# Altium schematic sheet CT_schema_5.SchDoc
size 385 x 355 mm
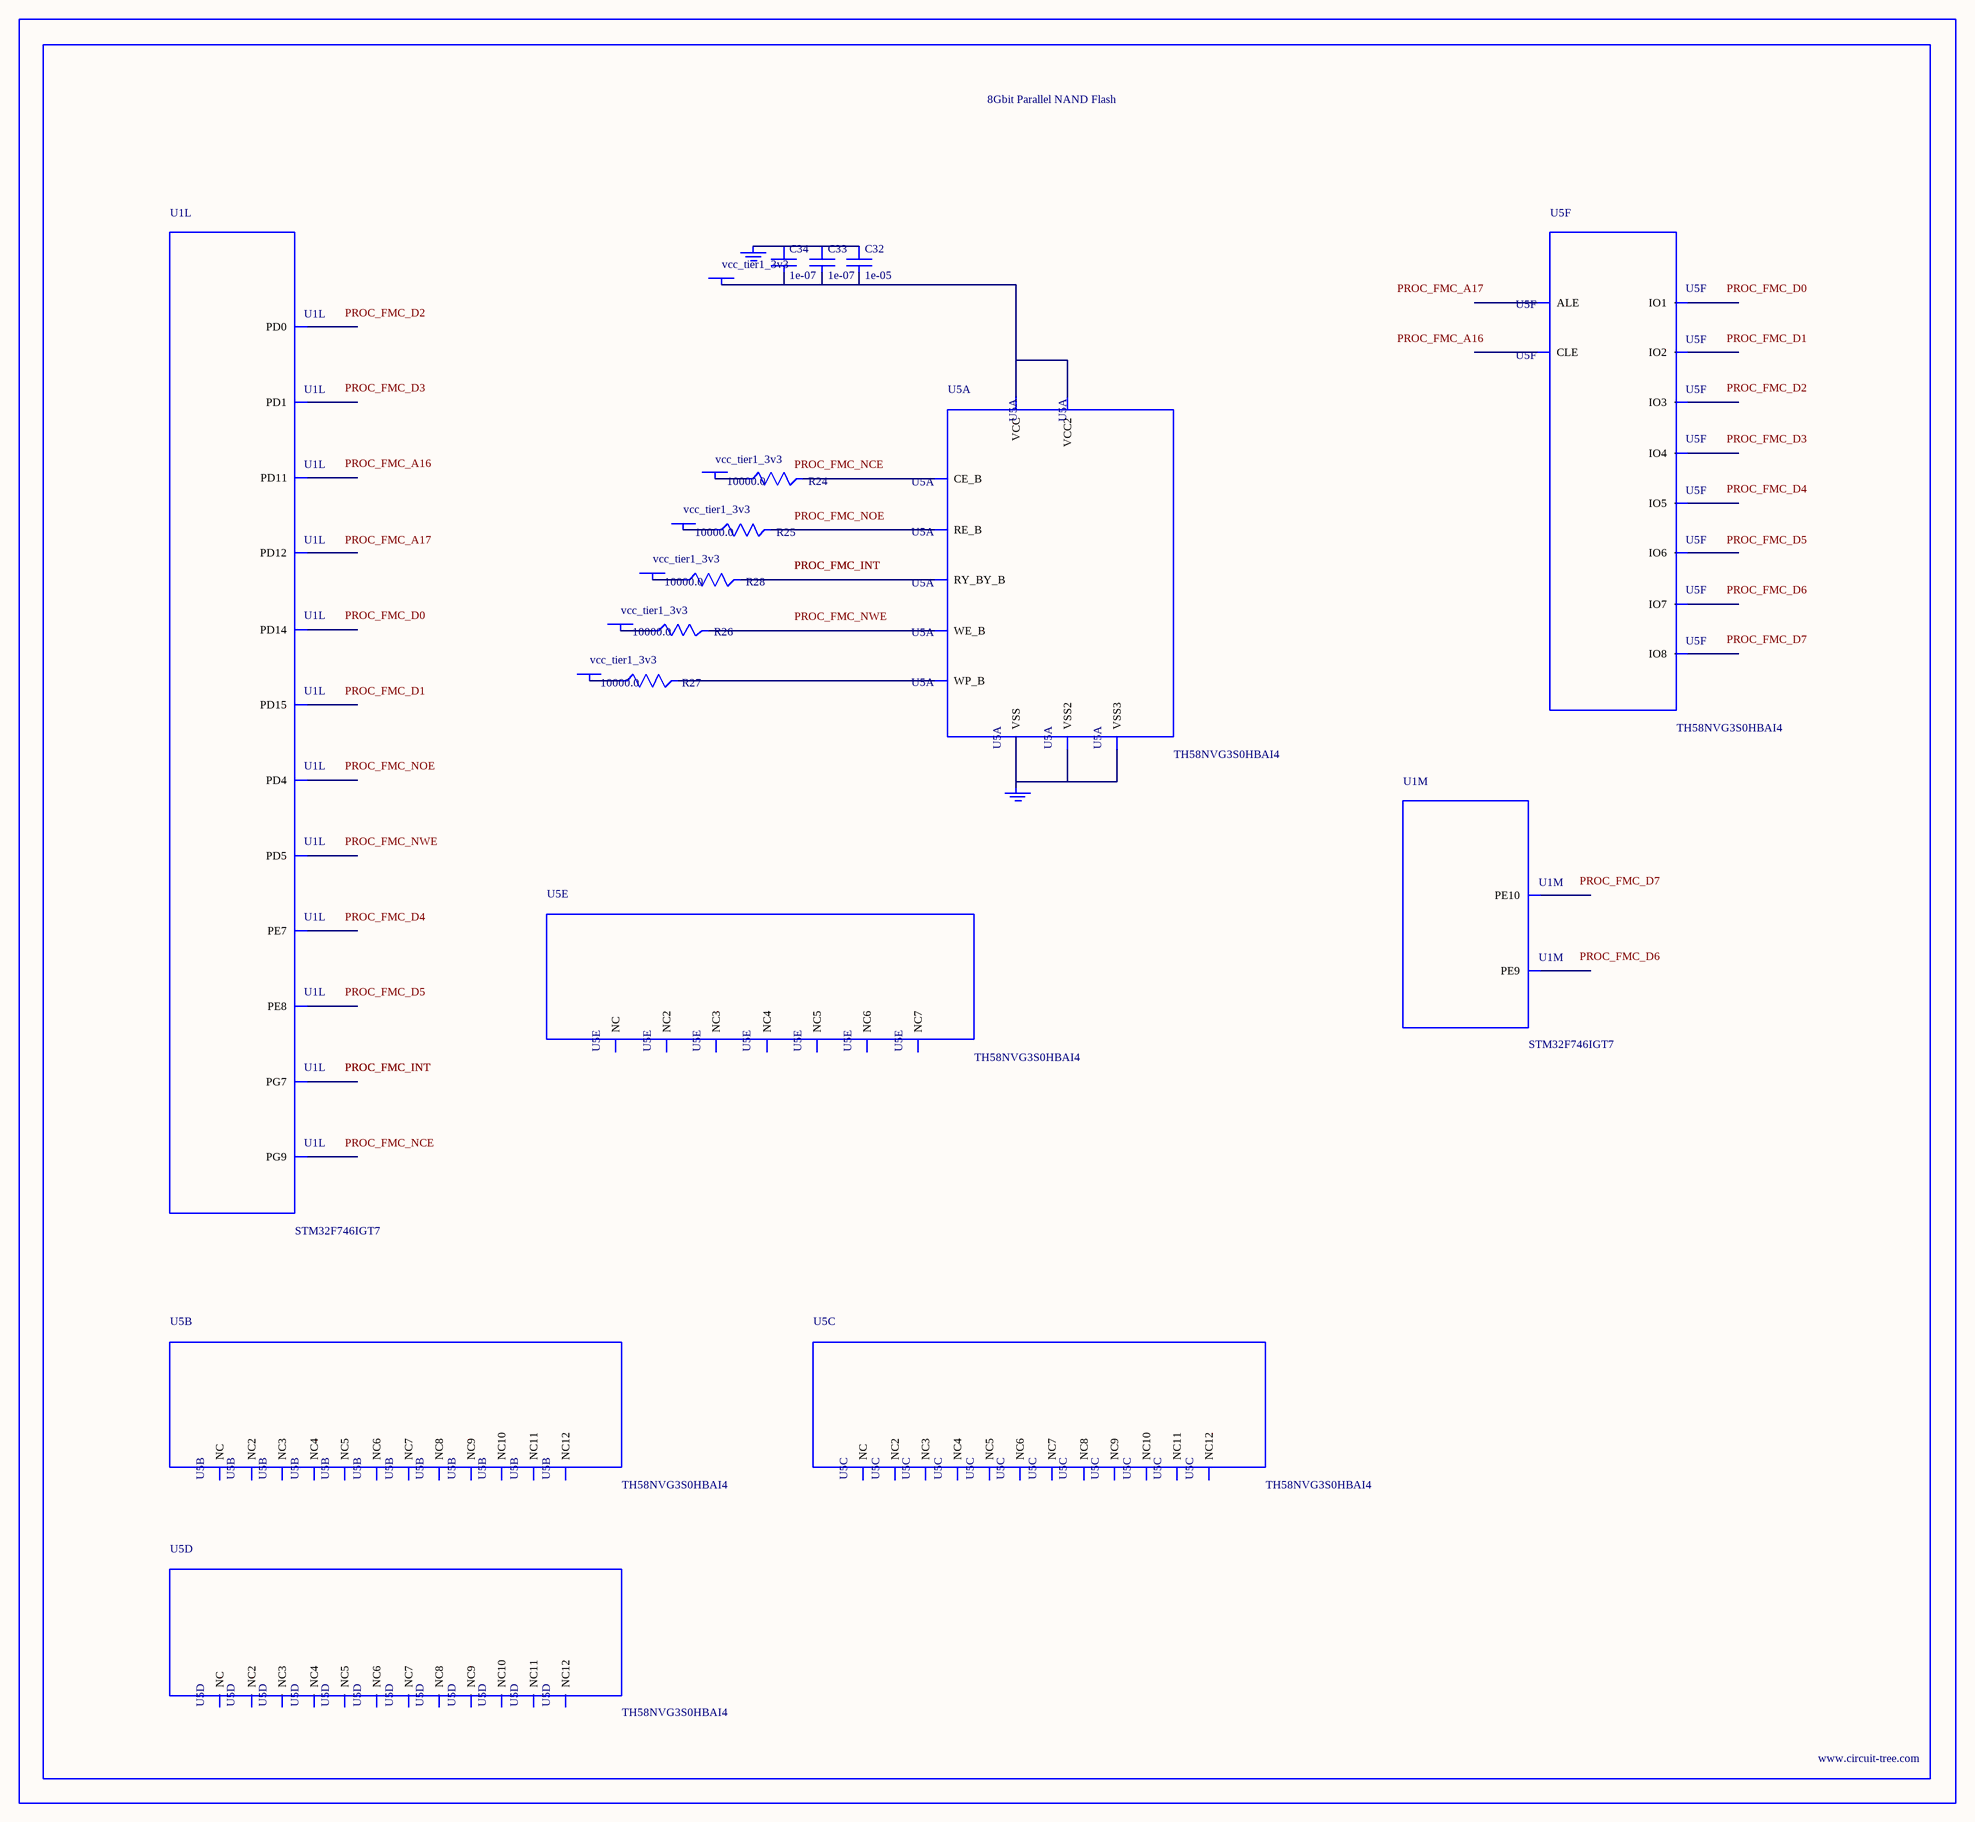
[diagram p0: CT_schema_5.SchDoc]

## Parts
BORDER4  (no value)
C32  1e-05  [C0805]
C33  1e-07  [C0402]
C34  1e-07  [C0402]
GND_INSTANCE_4_0  (no value)
GND_INSTANCE_4_1  (no value)
POWER_INSTANCE_4_0  vcc_tier1_3v3
POWER_INSTANCE_4_1  vcc_tier1_3v3
POWER_INSTANCE_4_2  vcc_tier1_3v3
POWER_INSTANCE_4_3  vcc_tier1_3v3
POWER_INSTANCE_4_4  vcc_tier1_3v3
POWER_INSTANCE_4_5  vcc_tier1_3v3
R24  10000.0  [R0603]
R25  10000.0  [R0603]
R26  10000.0  [R0603]
R27  10000.0  [R0603]
R28  10000.0  [R0603]
U1  STM32F746IGT7  [LQFP176]  (parts L,M of 15)
U5  TH58NVG3S0HBAI4  [TH58NVG3S0HBAI4]  (parts A,B,C,D,E,F of 6)

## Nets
NetC32_1: C32.1 C33.1 C34.1 GND_INSTANCE_4_0.0(GND)
NetC32_2: C32.2 C33.2 C34.2 POWER_INSTANCE_4_5.0(PWR) U5.H8(VCC) U5.J6(VCC2)
NetGND_INSTANCE_4_1_0: GND_INSTANCE_4_1.0(GND) U5.C5(VSS) U5.K3(VSS2) U5.K8(VSS3)
NetPOWER_INSTANCE_4_0_0: POWER_INSTANCE_4_0.0(PWR) R24.1
NetPOWER_INSTANCE_4_1_0: POWER_INSTANCE_4_1.0(PWR) R25.1
NetPOWER_INSTANCE_4_2_0: POWER_INSTANCE_4_2.0(PWR) R26.1
NetPOWER_INSTANCE_4_3_0: POWER_INSTANCE_4_3.0(PWR) R27.1
NetPOWER_INSTANCE_4_4_0: POWER_INSTANCE_4_4.0(PWR) R28.1
NetR24_2: R24.2 U5.C6(CE_B)
NetR25_2: R25.2 U5.D4(RE_B)
NetR26_2: R26.2 U5.C7(WE_B)
NetR27_2: R27.2 U5.C3(WP_B)
NetR28_2: R28.2 U5.C8(RY_BY_B)

Not connected (* = marked no-connect by the designer): U1 68(PE7) 69(PE8) 70(PE9) 73(PE10) 99(PD11) 100(PD12) 104(PD14) 105(PD15) 111(PG7) 142(PD0) 143(PD1) 146(PD4) 147(PD5) 152(PG9); U5 A1(NC) A2(NC3) A9(NC4) A10(NC2) B1(NC5) B9(NC7) B10(NC6) C4(ALE) D3(NC8) D5(CLE) D6(NC9) D7(NC10) D8(NC11) E3(NC12) E4(NC) E5(NC2) E6(NC3) E7(NC4) E8(NC5) F3(NC6) F4(NC7) F5(NC8) F6(NC9) F7(NC10) F8(NC11) G3(NC12) G4(NC) G5(NC2) G6(NC3) G7(NC4) G8(NC5) H3(NC6) H4(IO1) H5(NC7) H6(NC8) H7(NC9) J3(NC10) J4(IO2) J5(NC11) J7(IO6) J8(IO8) K4(IO3) K5(IO4) K6(IO5) K7(IO7) L1(NC12) L2(NC2) L9(NC3) L10(NC) M1(NC4) M2(NC6) M9(NC7) M10(NC5)

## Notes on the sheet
- Labels drawn without touching a wire or pin: PROC_FMC_A16, PROC_FMC_A17, PROC_FMC_D0, PROC_FMC_D1, PROC_FMC_D2, PROC_FMC_D3, PROC_FMC_D4, PROC_FMC_D5, PROC_FMC_D6, PROC_FMC_D7, PROC_FMC_NCE, PROC_FMC_NOE, PROC_FMC_NWE

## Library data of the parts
BORDER4 = BORDER_PAGE4
C32 = C0805C106K8RACTU
C33 C34 = C0402C104K3RACTU
GND_INSTANCE_4_0 GND_INSTANCE_4_1 = GND
POWER_INSTANCE_4_0-POWER_INSTANCE_4_5 = PWR
R24-R28 = RC0603JR-0710KL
